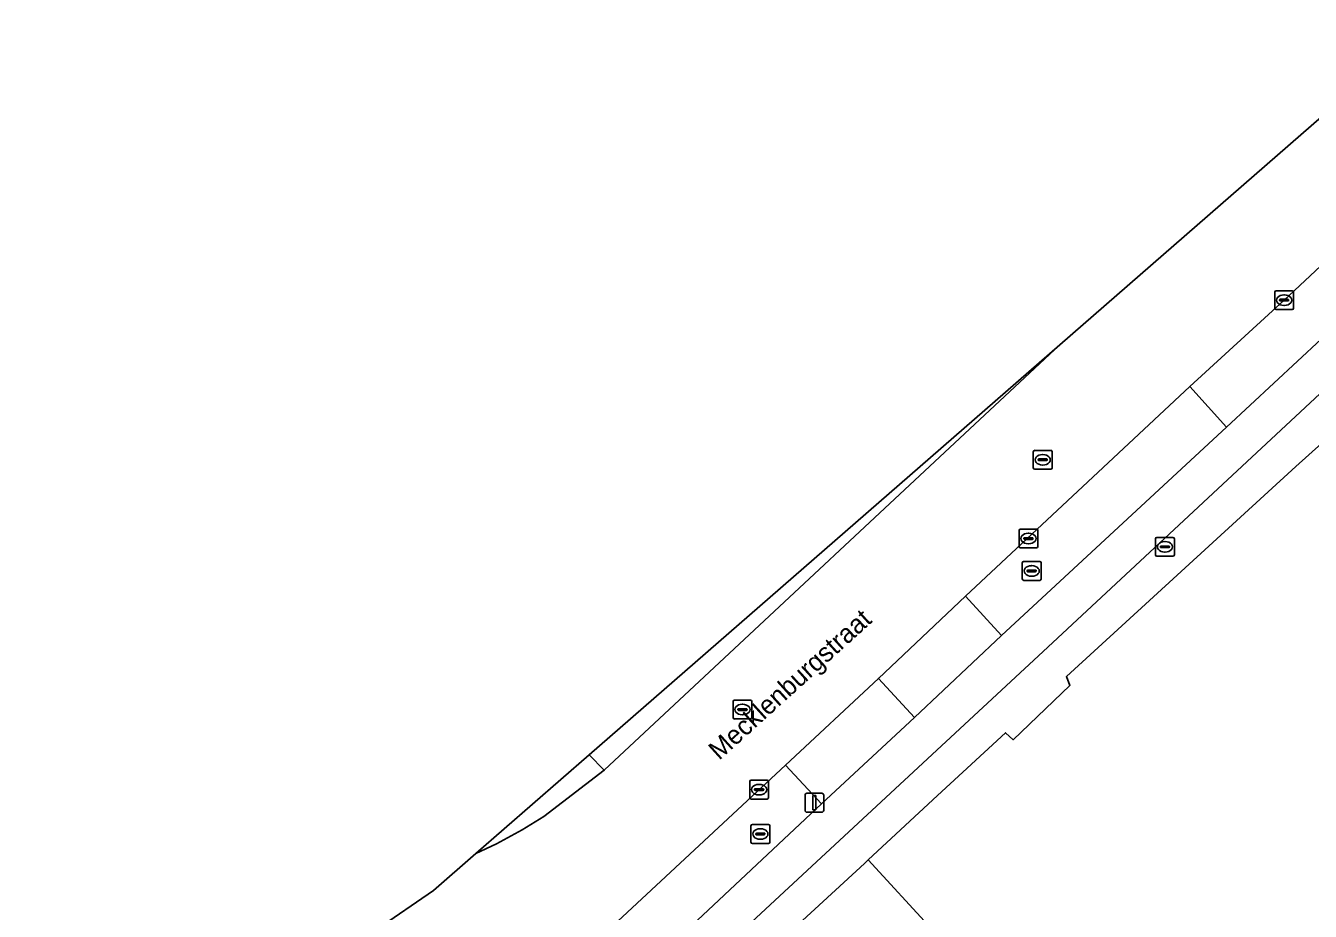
# Model space of a CAD drawing. Extents: x 160102 to 160934, y 382045 to 382923.
# Drawn here: x 160604 to 160672.1, y 382758.2 to 382805.1 of the extents above; entities that cross this region are included whole.
import ezdxf

# ---------------------------------------------------------------- set-up
doc = ezdxf.new("R2010")
doc.units = 0
for name, color, linetype in [('IMGEO_Brandkraan', 7, 'Continuous'), ('IMGEO_Erf', 7, 'Continuous'), ('IMGEO_Fietspad_gesloten', 7, 'Continuous'), ('IMGEO_Kolk', 7, 'Continuous'), ('IMGEO_Lichtmast', 7, 'Continuous'), ('IMGEO_Openbare_ruimte_label', 7, 'Continuous'), ('IMGEO_Pand', 7, 'Continuous'), ('IMGEO_Parkeervlak_open', 7, 'Continuous'), ('IMGEO_Rijbaan_lokaal_gesloten', 7, 'Continuous'), ('IMGEO_Rioolput', 7, 'Continuous'), ('IMGEO_Voetpad_open', 7, 'Continuous')]:
    doc.layers.add(name, color=color, linetype=linetype)

msp = doc.modelspace()

# ---------------------------------------------------------------- linework, layer by layer
at = {"layer": 'IMGEO_Brandkraan'}
for p, q in [((160663.943, 382778.016), (160664.795, 382778.016)), ((160663.868, 382777.09), (160663.868, 382777.942)), ((160664.127, 382777.51), (160664.127, 382777.522)), ((160664.565, 382777.473), (160664.167, 382777.473)), ((160664.17, 382777.559), (160664.568, 382777.559)), ((160664.356, 382777.796), (160664.381, 382777.796)), ((160664.611, 382777.522), (160664.611, 382777.51)), ((160664.869, 382777.942), (160664.869, 382777.09)), ((160664.795, 382777.016), (160663.943, 382777.016)), ((160664.379, 382777.236), (160664.354, 382777.236))]:
    msp.add_line(p, q, dxfattribs=at)
for points in [[(160663.943, 382778.016), (160664.795, 382778.016)], [(160663.868, 382777.09), (160663.868, 382777.942)], [(160664.869, 382777.942), (160664.869, 382777.09)], [(160664.795, 382777.016), (160663.943, 382777.016)]]:
    msp.add_lwpolyline(points, dxfattribs=at)
for centre, radius, start, end in [((160663.945, 382777.94), 0.0765, 91.55205, 178.44795), ((160663.945, 382777.94), 0.0765, 91.55205, 178.44795), ((160664.793, 382777.94), 0.0765, 1.55205, 88.44795), ((160664.793, 382777.94), 0.0765, 1.55205, 88.44795), ((160664.167, 382777.519), 0.0403, 85.87752, 175.75265), ((160664.164, 382777.509), 0.0366, 178.93798, 274.71019), ((160664.568, 382777.516), 0.043, 264.86636, 352.45326), ((160664.572, 382777.521), 0.0386, 1.73085, 96.63898), ((160663.945, 382777.092), 0.0765, 181.55205, 268.44795), ((160663.945, 382777.092), 0.0765, 181.55205, 268.44795), ((160664.793, 382777.092), 0.0765, 271.55205, 358.44795), ((160664.793, 382777.092), 0.0765, 271.55205, 358.44795)]:
    msp.add_arc(centre, radius, start, end, dxfattribs=at)
for centre, major_axis, ratio, start_param, end_param in [((160664.355, 382777.516), (-0.387, 0.002), 0.722429, 4.712389, 7.853982), ((160664.38, 382777.516), (-0.39, 0.002), 0.717154, 1.570796, 4.712389)]:
    msp.add_ellipse(centre, major_axis=major_axis, ratio=ratio, start_param=start_param, end_param=end_param, dxfattribs=at)
at = {"layer": 'IMGEO_Erf'}
msp.add_lwpolyline([(160681.481, 382790.904), (160671.308, 382781.781), (160659.144, 382770.644), (160659.335, 382770.161), (160656.319, 382767.295), (160655.924, 382767.662), (160653.66, 382765.577), (160652.314, 382764.338), (160648.64, 382760.93), (160652.026, 382757.251), (160655.856, 382753.091), (160653.553, 382750.971), (160654.452, 382750), (160658.854, 382745.244), (160664.022, 382750), (160667.038, 382752.775), (160669.504, 382755.044), (160674.932, 382750)], dxfattribs=at)
at = {"layer": 'IMGEO_Fietspad_gesloten'}
for points in [[(160680.167, 382795.521), (160667.629, 382783.858), (160655.707, 382772.815), (160651.097, 382768.481), (160646.168, 382763.905), (160634.157, 382752.637), (160628.941, 382747.912), (160622.116, 382741.606), (160618.296, 382737.897), (160615.726, 382734.786), (160611, 382728.257), (160608.445, 382724.675), (160604.005, 382718.537)], [(160621.261, 382737.92), (160622.616, 382739.208), (160657.91, 382771.975), (160669.999, 382783.221), (160681.614, 382794.046)], [(160633.862, 382766.492), (160627.86, 382761.261), (160628.952, 382761.774), (160630.304, 382762.522), (160631.46, 382763.231), (160634.664, 382765.679), (160633.862, 382766.492)]]:
    msp.add_lwpolyline(points, dxfattribs=at)
at = {"layer": 'IMGEO_Kolk'}
for p, q in [((160670.184, 382790.161), (160670.184, 382791.013)), ((160670.259, 382791.087), (160671.111, 382791.087)), ((160671.185, 382791.013), (160671.185, 382790.161)), ((160670.443, 382790.581), (160670.443, 382790.593)), ((160670.881, 382790.544), (160670.483, 382790.544)), ((160670.486, 382790.63), (160670.884, 382790.63)), ((160670.695, 382790.307), (160670.67, 382790.307)), ((160670.672, 382790.867), (160670.697, 382790.867)), ((160670.927, 382790.593), (160670.927, 382790.581)), ((160671.111, 382790.087), (160670.259, 382790.087)), ((160656.636, 382777.53), (160656.636, 382778.382)), ((160656.711, 382778.456), (160657.563, 382778.456)), ((160657.124, 382778.236), (160657.149, 382778.236)), ((160657.637, 382778.382), (160657.637, 382777.53)), ((160657.563, 382777.456), (160656.711, 382777.456)), ((160656.895, 382777.95), (160656.895, 382777.962)), ((160657.333, 382777.913), (160656.935, 382777.913)), ((160656.938, 382777.999), (160657.336, 382777.999)), ((160657.147, 382777.676), (160657.122, 382777.676)), ((160657.379, 382777.962), (160657.379, 382777.95)), ((160642.366, 382764.227), (160642.366, 382765.079)), ((160642.441, 382765.153), (160643.293, 382765.153)), ((160643.367, 382765.079), (160643.367, 382764.227)), ((160642.625, 382764.647), (160642.625, 382764.659)), ((160643.063, 382764.61), (160642.665, 382764.61)), ((160642.668, 382764.696), (160643.066, 382764.696)), ((160642.854, 382764.933), (160642.879, 382764.933)), ((160643.109, 382764.659), (160643.109, 382764.647)), ((160643.293, 382764.153), (160642.441, 382764.153)), ((160642.877, 382764.373), (160642.852, 382764.373))]:
    msp.add_line(p, q, dxfattribs=at)
for points in [[(160670.184, 382790.161), (160670.184, 382791.013)], [(160670.259, 382791.087), (160671.111, 382791.087)], [(160671.185, 382791.013), (160671.185, 382790.161)], [(160671.111, 382790.087), (160670.259, 382790.087)], [(160656.636, 382777.53), (160656.636, 382778.382)], [(160656.711, 382778.456), (160657.563, 382778.456)], [(160657.637, 382778.382), (160657.637, 382777.53)], [(160657.563, 382777.456), (160656.711, 382777.456)], [(160642.366, 382764.227), (160642.366, 382765.079)], [(160642.441, 382765.153), (160643.293, 382765.153)], [(160643.367, 382765.079), (160643.367, 382764.227)], [(160643.293, 382764.153), (160642.441, 382764.153)]]:
    msp.add_lwpolyline(points, dxfattribs=at)
for centre, radius, start, end in [((160670.261, 382791.011), 0.0765, 91.55205, 178.44795), ((160670.261, 382791.011), 0.0765, 91.55205, 178.44795), ((160671.109, 382791.011), 0.0765, 1.55205, 88.44795), ((160671.109, 382791.011), 0.0765, 1.55205, 88.44795), ((160670.483, 382790.59), 0.0403, 85.87752, 175.75265), ((160670.48, 382790.58), 0.0366, 178.93798, 274.71019), ((160670.884, 382790.587), 0.043, 264.86636, 352.45326), ((160670.888, 382790.592), 0.0386, 1.73085, 96.63898), ((160670.261, 382790.163), 0.0765, 181.55205, 268.44795), ((160670.261, 382790.163), 0.0765, 181.55205, 268.44795), ((160671.109, 382790.163), 0.0765, 271.55205, 358.44795), ((160671.109, 382790.163), 0.0765, 271.55205, 358.44795), ((160656.713, 382778.38), 0.0765, 91.55205, 178.44795), ((160656.713, 382778.38), 0.0765, 91.55205, 178.44795), ((160657.561, 382778.38), 0.0765, 1.55205, 88.44795), ((160657.561, 382778.38), 0.0765, 1.55205, 88.44795), ((160656.713, 382777.532), 0.0765, 181.55205, 268.44795), ((160656.713, 382777.532), 0.0765, 181.55205, 268.44795), ((160656.935, 382777.959), 0.0403, 85.87752, 175.75265), ((160656.932, 382777.949), 0.0366, 178.93798, 274.71019), ((160657.336, 382777.956), 0.043, 264.86636, 352.45326), ((160657.34, 382777.961), 0.0386, 1.73085, 96.63898), ((160657.561, 382777.532), 0.0765, 271.55205, 358.44795), ((160657.561, 382777.532), 0.0765, 271.55205, 358.44795), ((160642.443, 382765.077), 0.0765, 91.55205, 178.44795), ((160642.443, 382765.077), 0.0765, 91.55205, 178.44795), ((160643.291, 382765.077), 0.0765, 1.55205, 88.44795), ((160643.291, 382765.077), 0.0765, 1.55205, 88.44795), ((160642.665, 382764.656), 0.0403, 85.87752, 175.75265), ((160642.662, 382764.646), 0.0366, 178.93798, 274.71019), ((160643.066, 382764.653), 0.043, 264.86636, 352.45326), ((160643.07, 382764.658), 0.0386, 1.73085, 96.63898), ((160642.443, 382764.229), 0.0765, 181.55205, 268.44795), ((160642.443, 382764.229), 0.0765, 181.55205, 268.44795), ((160643.291, 382764.229), 0.0765, 271.55205, 358.44795), ((160643.291, 382764.229), 0.0765, 271.55205, 358.44795)]:
    msp.add_arc(centre, radius, start, end, dxfattribs=at)
for centre, major_axis, ratio, start_param, end_param in [((160670.671, 382790.587), (-0.387, 0.002), 0.722429, 4.712389, 7.853982), ((160670.696, 382790.587), (-0.39, 0.002), 0.717154, 1.570796, 4.712389), ((160657.123, 382777.956), (-0.387, 0.002), 0.722429, 4.712389, 7.853982), ((160657.148, 382777.956), (-0.39, 0.002), 0.717154, 1.570796, 4.712389), ((160642.853, 382764.653), (-0.387, 0.002), 0.722429, 4.712389, 7.853982), ((160642.878, 382764.653), (-0.39, 0.002), 0.717154, 1.570796, 4.712389)]:
    msp.add_ellipse(centre, major_axis=major_axis, ratio=ratio, start_param=start_param, end_param=end_param, dxfattribs=at)
at = {"layer": 'IMGEO_Lichtmast'}
for p, q in [((160645.398, 382764.459), (160646.188, 382764.459)), ((160646.188, 382764.459), (160645.398, 382764.459)), ((160645.298, 382763.559), (160645.298, 382764.359)), ((160645.298, 382764.359), (160645.298, 382763.559)), ((160646.288, 382764.359), (160646.288, 382763.559)), ((160646.288, 382763.559), (160646.288, 382764.359)), ((160646.188, 382763.459), (160645.398, 382763.459)), ((160645.398, 382763.459), (160646.188, 382763.459))]:
    msp.add_line(p, q, dxfattribs=at)
msp.add_lwpolyline([(160645.718, 382764.334), (160645.868, 382764.334), (160645.868, 382763.584), (160645.718, 382763.584), (160645.718, 382764.334)], dxfattribs=at)
for centre, start, end in [((160645.398, 382764.359), 90, 180), ((160645.398, 382764.359), 90, 180), ((160646.188, 382764.359), 0, 90), ((160646.188, 382764.359), 360, 90), ((160645.398, 382763.559), 180, 270), ((160645.398, 382763.559), 180, 270), ((160646.188, 382763.559), 270, 0), ((160646.188, 382763.559), 270, 0)]:
    msp.add_arc(centre, 0.1, start, end, dxfattribs=at)
at = {"layer": 'IMGEO_Pand'}
msp.add_lwpolyline([(160674.932, 382750), (160669.504, 382755.044), (160667.038, 382752.775), (160664.022, 382750), (160658.854, 382745.244), (160654.452, 382750), (160653.553, 382750.971), (160655.856, 382753.091), (160652.026, 382757.251), (160648.64, 382760.93), (160648.442, 382760.747), (160644.069, 382756.709), (160650.265, 382750), (160653.244, 382746.775), (160651.139, 382744.83), (160651.354, 382744.596), (160651.849, 382743.636), (160654.674, 382738.16), (160658.261, 382734.263), (160654.372, 382730.683), (160664.965, 382720.029), (160686.175, 382739.553)], close=True, dxfattribs=at)
at = {"layer": 'IMGEO_Parkeervlak_open'}
msp.add_lwpolyline([(160683.651, 382802.717), (160670.685, 382790.587), (160665.69, 382786.016), (160667.629, 382783.858), (160680.167, 382795.521)], dxfattribs=at)
for points in [[(160653.803, 382774.9), (160649.188, 382770.545), (160651.097, 382768.481), (160655.707, 382772.815)], [(160644.258, 382765.947), (160632.081, 382754.608), (160634.157, 382752.637), (160646.168, 382763.905)]]:
    msp.add_lwpolyline(points, close=True, dxfattribs=at)
at = {"layer": 'IMGEO_Rijbaan_lokaal_gesloten'}
for points in [[(160835.083, 382905.864), (160802.421, 382887.508), (160718.808, 382840.517), (160673.346, 382800.899), (160658.793, 382788.217), (160634.664, 382765.679), (160631.46, 382763.231), (160630.304, 382762.522), (160628.952, 382761.774), (160627.86, 382761.261), (160625.615, 382759.305), (160622.622, 382757.268), (160622.624, 382757.265)], [(160623.722, 382750.857), (160605.678, 382735.154), (160607.777, 382732.272), (160623.499, 382745.883), (160627.337, 382749.441), (160632.081, 382754.608), (160644.258, 382765.947), (160649.188, 382770.545), (160653.803, 382774.9), (160665.69, 382786.016), (160670.685, 382790.587), (160683.651, 382802.717)], [(160658.793, 382788.217), (160633.862, 382766.492), (160634.664, 382765.679), (160658.793, 382788.217)]]:
    msp.add_lwpolyline(points, dxfattribs=at)
at = {"layer": 'IMGEO_Rioolput'}
for p, q in [((160657.392, 382781.703), (160657.392, 382782.555)), ((160657.467, 382782.629), (160658.319, 382782.629)), ((160657.651, 382782.123), (160657.651, 382782.135)), ((160658.089, 382782.086), (160657.691, 382782.086)), ((160657.694, 382782.172), (160658.092, 382782.172)), ((160657.88, 382782.409), (160657.905, 382782.409)), ((160658.135, 382782.135), (160658.135, 382782.123)), ((160658.393, 382782.555), (160658.393, 382781.703)), ((160658.319, 382781.629), (160657.467, 382781.629)), ((160657.903, 382781.849), (160657.878, 382781.849)), ((160656.808, 382775.813), (160656.808, 382776.665)), ((160656.883, 382776.739), (160657.735, 382776.739)), ((160657.809, 382776.665), (160657.809, 382775.813)), ((160657.067, 382776.233), (160657.067, 382776.245)), ((160657.505, 382776.196), (160657.107, 382776.196)), ((160657.11, 382776.282), (160657.508, 382776.282)), ((160657.319, 382775.959), (160657.294, 382775.959)), ((160657.296, 382776.519), (160657.321, 382776.519)), ((160657.551, 382776.245), (160657.551, 382776.233)), ((160657.735, 382775.739), (160656.883, 382775.739)), ((160641.483, 382768.469), (160641.483, 382769.321)), ((160641.558, 382769.395), (160642.41, 382769.395)), ((160641.971, 382769.175), (160641.996, 382769.175)), ((160642.484, 382769.321), (160642.484, 382768.469)), ((160641.742, 382768.889), (160641.742, 382768.901)), ((160642.18, 382768.852), (160641.782, 382768.852)), ((160641.785, 382768.938), (160642.183, 382768.938)), ((160641.994, 382768.615), (160641.969, 382768.615)), ((160642.226, 382768.901), (160642.226, 382768.889)), ((160642.41, 382768.395), (160641.558, 382768.395)), ((160642.433, 382761.877), (160642.433, 382762.729)), ((160642.508, 382762.803), (160643.36, 382762.803)), ((160642.735, 382762.346), (160643.133, 382762.346)), ((160642.921, 382762.583), (160642.946, 382762.583)), ((160643.434, 382762.729), (160643.434, 382761.877)), ((160643.36, 382761.803), (160642.508, 382761.803)), ((160642.692, 382762.297), (160642.692, 382762.309)), ((160643.13, 382762.26), (160642.732, 382762.26)), ((160642.944, 382762.023), (160642.919, 382762.023)), ((160643.176, 382762.309), (160643.176, 382762.297))]:
    msp.add_line(p, q, dxfattribs=at)
for points in [[(160657.392, 382781.703), (160657.392, 382782.555)], [(160657.467, 382782.629), (160658.319, 382782.629)], [(160658.393, 382782.555), (160658.393, 382781.703)], [(160658.319, 382781.629), (160657.467, 382781.629)], [(160656.808, 382775.813), (160656.808, 382776.665)], [(160656.883, 382776.739), (160657.735, 382776.739)], [(160657.809, 382776.665), (160657.809, 382775.813)], [(160657.735, 382775.739), (160656.883, 382775.739)], [(160641.483, 382768.469), (160641.483, 382769.321)], [(160641.558, 382769.395), (160642.41, 382769.395)], [(160642.484, 382769.321), (160642.484, 382768.469)], [(160642.41, 382768.395), (160641.558, 382768.395)], [(160642.433, 382761.877), (160642.433, 382762.729)], [(160642.508, 382762.803), (160643.36, 382762.803)], [(160643.434, 382762.729), (160643.434, 382761.877)], [(160643.36, 382761.803), (160642.508, 382761.803)]]:
    msp.add_lwpolyline(points, dxfattribs=at)
for centre, radius, start, end in [((160657.469, 382782.553), 0.0765, 91.55205, 178.44795), ((160657.469, 382782.553), 0.0765, 91.55205, 178.44795), ((160657.691, 382782.132), 0.0403, 85.87752, 175.75265), ((160657.688, 382782.122), 0.0366, 178.93798, 274.71019), ((160658.092, 382782.129), 0.043, 264.86636, 352.45326), ((160658.096, 382782.134), 0.0386, 1.73085, 96.63898), ((160658.317, 382782.553), 0.0765, 1.55205, 88.44795), ((160658.317, 382782.553), 0.0765, 1.55205, 88.44795), ((160657.469, 382781.705), 0.0765, 181.55205, 268.44795), ((160657.469, 382781.705), 0.0765, 181.55205, 268.44795), ((160658.317, 382781.705), 0.0765, 271.55205, 358.44795), ((160658.317, 382781.705), 0.0765, 271.55205, 358.44795), ((160656.885, 382776.663), 0.0765, 91.55205, 178.44795), ((160656.885, 382776.663), 0.0765, 91.55205, 178.44795), ((160657.733, 382776.663), 0.0765, 1.55205, 88.44795), ((160657.733, 382776.663), 0.0765, 1.55205, 88.44795), ((160657.107, 382776.242), 0.0403, 85.87752, 175.75265), ((160657.104, 382776.232), 0.0366, 178.93798, 274.71019), ((160657.508, 382776.239), 0.043, 264.86636, 352.45326), ((160657.512, 382776.244), 0.0386, 1.73085, 96.63898), ((160656.885, 382775.815), 0.0765, 181.55205, 268.44795), ((160656.885, 382775.815), 0.0765, 181.55205, 268.44795), ((160657.733, 382775.815), 0.0765, 271.55205, 358.44795), ((160657.733, 382775.815), 0.0765, 271.55205, 358.44795), ((160641.56, 382769.319), 0.0765, 91.55205, 178.44795), ((160641.56, 382769.319), 0.0765, 91.55205, 178.44795), ((160642.408, 382769.319), 0.0765, 1.55205, 88.44795), ((160642.408, 382769.319), 0.0765, 1.55205, 88.44795), ((160641.782, 382768.898), 0.0403, 85.87752, 175.75265), ((160641.779, 382768.888), 0.0366, 178.93798, 274.71019), ((160642.183, 382768.895), 0.043, 264.86636, 352.45326), ((160642.187, 382768.9), 0.0386, 1.73085, 96.63898), ((160641.56, 382768.471), 0.0765, 181.55205, 268.44795), ((160641.56, 382768.471), 0.0765, 181.55205, 268.44795), ((160642.408, 382768.471), 0.0765, 271.55205, 358.44795), ((160642.408, 382768.471), 0.0765, 271.55205, 358.44795), ((160642.51, 382762.727), 0.0765, 91.55205, 178.44795), ((160642.51, 382762.727), 0.0765, 91.55205, 178.44795), ((160642.732, 382762.306), 0.0403, 85.87752, 175.75265), ((160643.137, 382762.308), 0.0386, 1.73085, 96.63898), ((160643.358, 382762.727), 0.0765, 1.55205, 88.44795), ((160643.358, 382762.727), 0.0765, 1.55205, 88.44795), ((160642.51, 382761.879), 0.0765, 181.55205, 268.44795), ((160642.51, 382761.879), 0.0765, 181.55205, 268.44795), ((160642.729, 382762.296), 0.0366, 178.93798, 274.71019), ((160643.133, 382762.303), 0.043, 264.86636, 352.45326), ((160643.358, 382761.879), 0.0765, 271.55205, 358.44795), ((160643.358, 382761.879), 0.0765, 271.55205, 358.44795)]:
    msp.add_arc(centre, radius, start, end, dxfattribs=at)
for centre, major_axis, ratio, start_param, end_param in [((160657.879, 382782.129), (-0.387, 0.002), 0.722429, 4.712389, 7.853982), ((160657.904, 382782.129), (-0.39, 0.002), 0.717154, 1.570796, 4.712389), ((160657.295, 382776.239), (-0.387, 0.002), 0.722429, 4.712389, 7.853982), ((160657.32, 382776.239), (-0.39, 0.002), 0.717154, 1.570796, 4.712389), ((160641.97, 382768.895), (-0.387, 0.002), 0.722429, 4.712389, 7.853982), ((160641.995, 382768.895), (-0.39, 0.002), 0.717154, 1.570796, 4.712389), ((160642.92, 382762.303), (-0.387, 0.002), 0.722429, 4.712389, 7.853982), ((160642.945, 382762.303), (-0.39, 0.002), 0.717154, 1.570796, 4.712389)]:
    msp.add_ellipse(centre, major_axis=major_axis, ratio=ratio, start_param=start_param, end_param=end_param, dxfattribs=at)
at = {"layer": 'IMGEO_Voetpad_open'}
for points in [[(160659.144, 382770.644), (160671.308, 382781.781), (160681.481, 382790.904), (160682.397, 382791.725), (160682.484, 382791.808), (160682.548, 382791.869), (160690.093, 382799.043), (160694.961, 382803.958), (160699.055, 382808.551), (160699.072, 382808.567), (160701.633, 382810.889), (160705.883, 382814.742), (160715.677, 382823.578), (160713.713, 382825.78), (160701.334, 382814.217), (160699.691, 382815.96), (160694.026, 382810.658), (160696.114, 382808.585), (160689.462, 382802.186), (160688.305, 382801.004), (160686.824, 382802.529), (160686.599, 382802.169), (160686.157, 382801.331), (160683.431, 382796.237)], [(160681.614, 382794.046), (160669.999, 382783.221), (160657.91, 382771.975), (160622.616, 382739.208), (160623.862, 382738.235), (160622.866, 382736.832), (160621.261, 382737.92)], [(160605.334, 382714.432), (160606.999, 382711.598), (160608.819, 382712.639), (160608.036, 382713.994), (160627.863, 382741.339), (160635.89, 382749.157), (160636.803, 382750), (160640.109, 382753.053), (160644.069, 382756.709), (160648.442, 382760.747), (160648.64, 382760.93), (160652.314, 382764.338), (160653.66, 382765.577), (160655.924, 382767.662), (160656.319, 382767.295), (160659.335, 382770.161), (160659.144, 382770.644)]]:
    msp.add_lwpolyline(points, dxfattribs=at)
for points in [[(160665.69, 382786.016), (160653.803, 382774.9), (160655.707, 382772.815), (160667.629, 382783.858)], [(160646.168, 382763.905), (160651.097, 382768.481), (160649.188, 382770.545), (160644.258, 382765.947)]]:
    msp.add_lwpolyline(points, close=True, dxfattribs=at)

# ---------------------------------------------------------------- texts
at = {"layer": 'IMGEO_Openbare_ruimte_label'}
msp.add_text('Mecklenburgstraat', height=1, rotation=42.16188, dxfattribs=at).set_placement((160640.749, 382766.174))

doc.saveas('drawing.dxf')
